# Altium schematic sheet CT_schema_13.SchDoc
size 389 x 385 mm
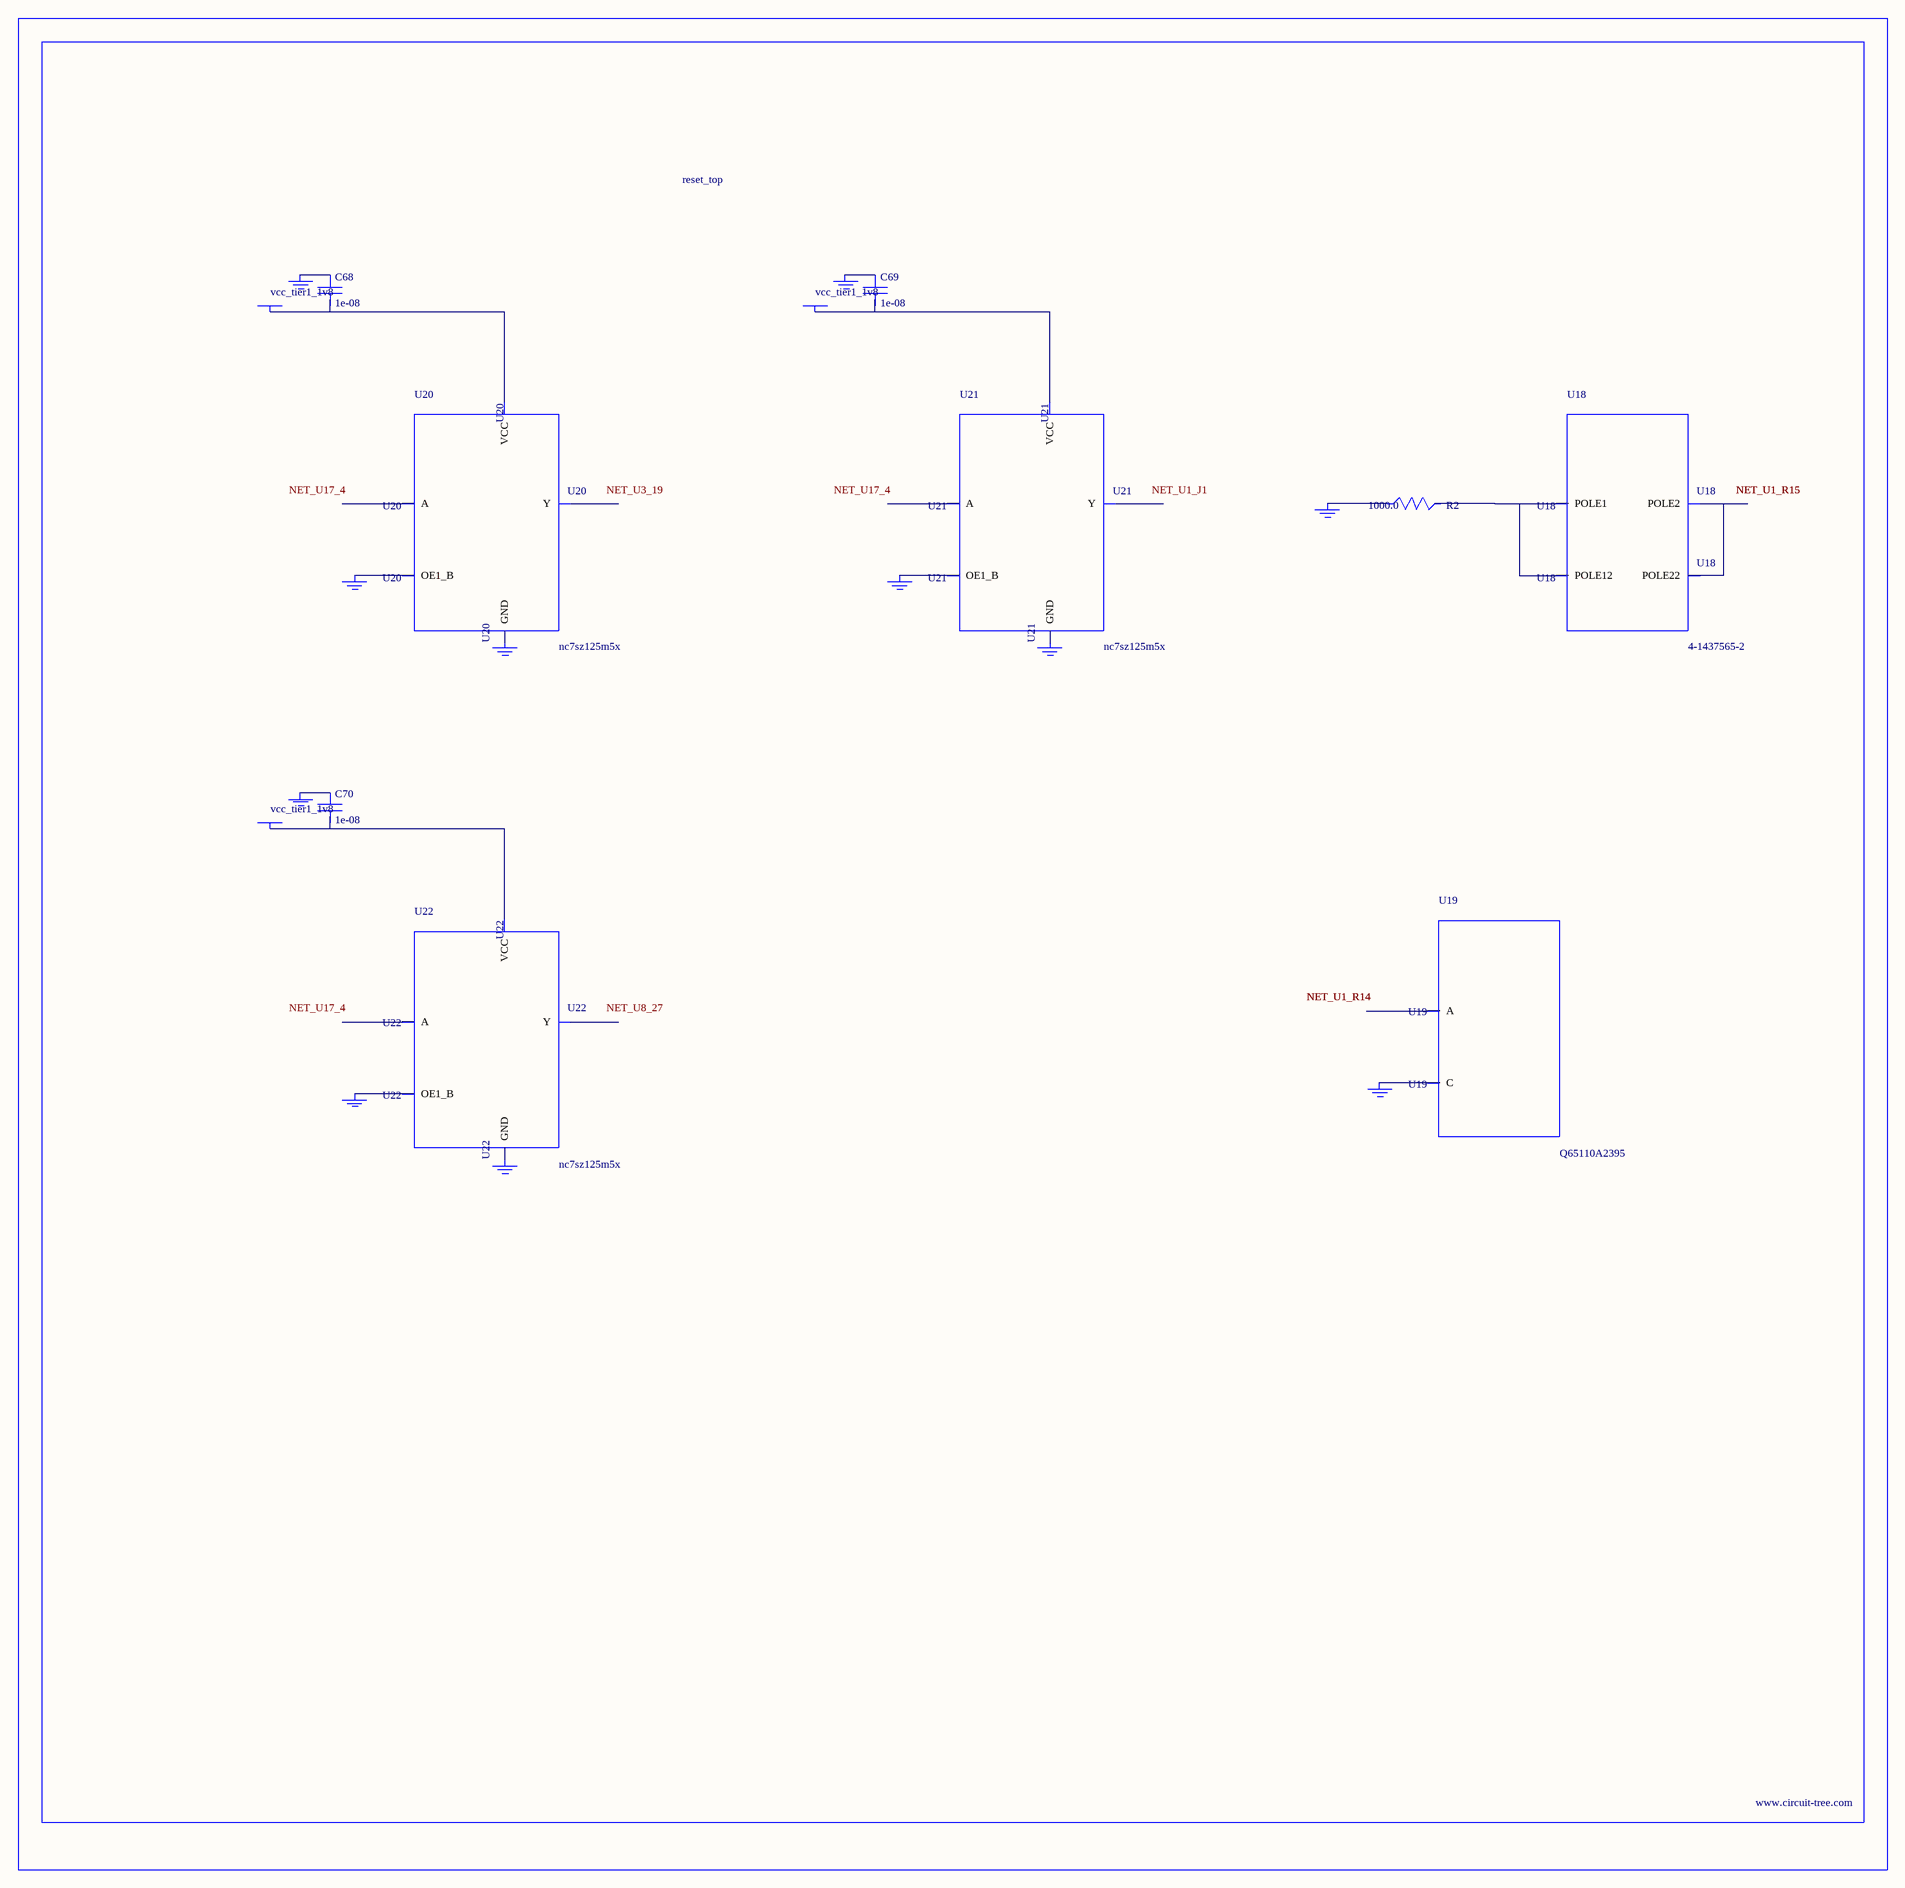
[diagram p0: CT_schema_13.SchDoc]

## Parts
BORDER12  (no value)
C68  1e-08  [C0402]
C69  1e-08  [C0402]
C70  1e-08  [C0402]
GND_INSTANCE_12_0  (no value)
GND_INSTANCE_12_1  (no value)
GND_INSTANCE_12_2  (no value)
GND_INSTANCE_12_3  (no value)
GND_INSTANCE_12_4  (no value)
GND_INSTANCE_12_5  (no value)
GND_INSTANCE_12_6  (no value)
GND_INSTANCE_12_7  (no value)
GND_INSTANCE_12_8  (no value)
GND_INSTANCE_12_9  (no value)
GND_INSTANCE_12_10  (no value)
POWER_INSTANCE_12_0  vcc_tier1_1v8
POWER_INSTANCE_12_1  vcc_tier1_1v8
POWER_INSTANCE_12_2  vcc_tier1_1v8
R2  1000.0  [R0603]
U18  4-1437565-2  [SW_4-1437565-2]
U19  Q65110A2395  [LGM67K-G1J2-24-Z]
U20  nc7sz125m5x  [NC7SZ125M5X]
U21  nc7sz125m5x  [NC7SZ125M5X]
U22  nc7sz125m5x  [NC7SZ125M5X]

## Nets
NetC68_1: C68.1 GND_INSTANCE_12_2.0(GND)
NetC68_2: C68.2 POWER_INSTANCE_12_0.0(PWR) U20.5(VCC)
NetC69_1: C69.1 GND_INSTANCE_12_5.0(GND)
NetC69_2: C69.2 POWER_INSTANCE_12_1.0(PWR) U21.5(VCC)
NetC70_1: C70.1 GND_INSTANCE_12_8.0(GND)
NetC70_2: C70.2 POWER_INSTANCE_12_2.0(PWR) U22.5(VCC)
NetGND_INSTANCE_12_0_0: GND_INSTANCE_12_0.0(GND) R2.1
NetGND_INSTANCE_12_1_0: GND_INSTANCE_12_1.0(GND) U19.C
NetGND_INSTANCE_12_3_0: GND_INSTANCE_12_3.0(GND) U20.1(OE1_B)
NetGND_INSTANCE_12_4_0: GND_INSTANCE_12_4.0(GND) U20.3(GND)
NetGND_INSTANCE_12_6_0: GND_INSTANCE_12_6.0(GND) U21.1(OE1_B)
NetGND_INSTANCE_12_7_0: GND_INSTANCE_12_7.0(GND) U21.3(GND)
NetGND_INSTANCE_12_9_0: GND_INSTANCE_12_9.0(GND) U22.1(OE1_B)
NetGND_INSTANCE_12_10_0: GND_INSTANCE_12_10.0(GND) U22.3(GND)
NetR2_2: R2.2 U18.1(POLE1) U18.2(POLE12)
NetU18_3: U18.3(POLE2) U18.4(POLE22)

Not connected (* = marked no-connect by the designer): U19 A; U20 2(A) 4(Y); U21 2(A) 4(Y); U22 2(A) 4(Y)

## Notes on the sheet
- Labels drawn without touching a wire or pin: NET_U1_J1, NET_U3_19, NET_U8_27, NET_U17_4

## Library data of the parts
BORDER12 = BORDER_PAGE12
C68-C70 = C0402C103K3RAC
GND_INSTANCE_12_0-GND_INSTANCE_12_10 = GND
POWER_INSTANCE_12_0-POWER_INSTANCE_12_2 = PWR
R2 = RC0603JR-071KL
